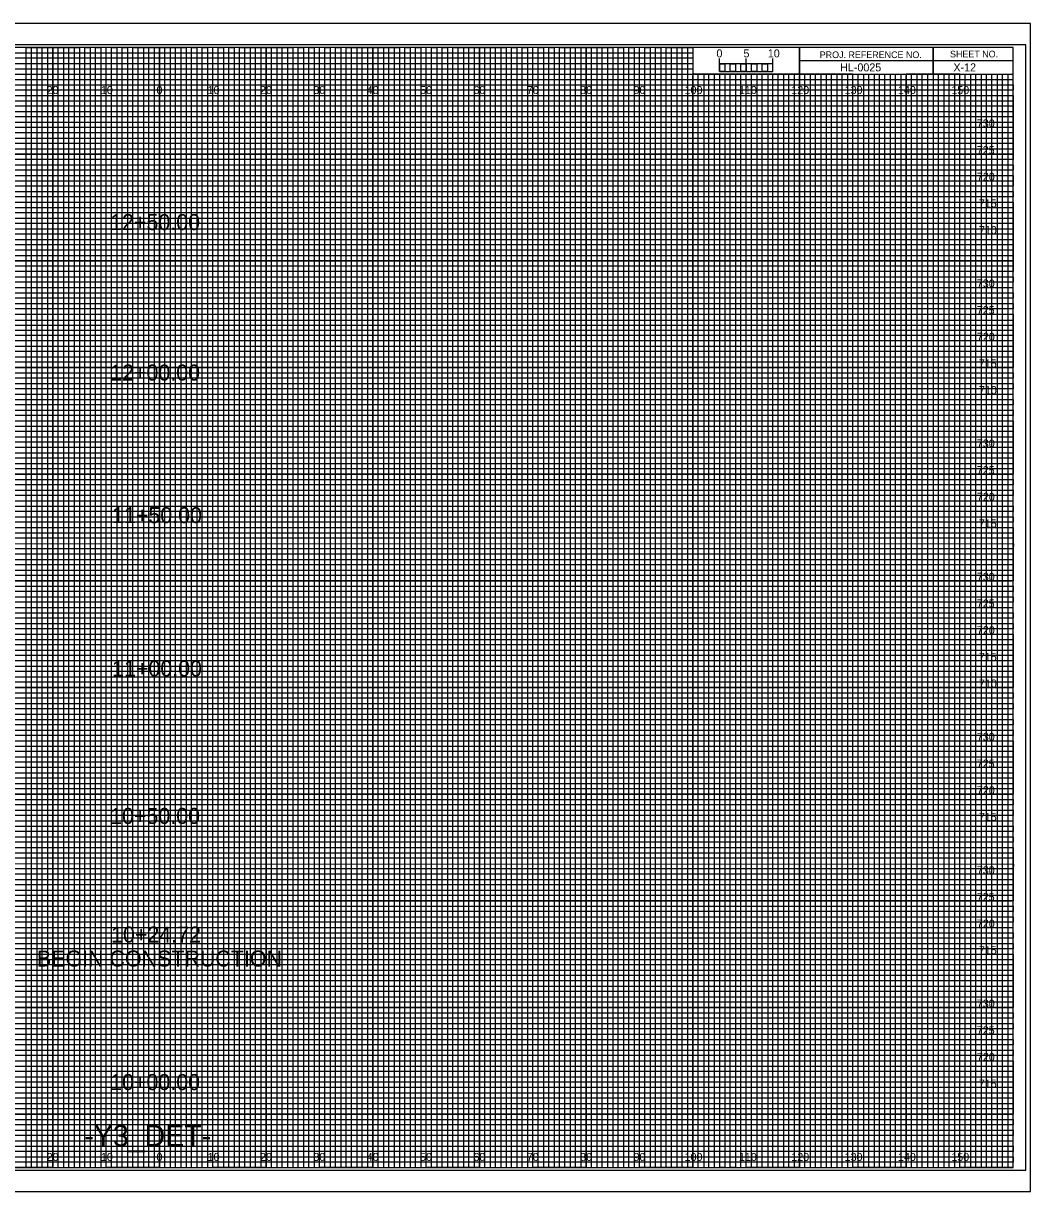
# Model space of a CAD drawing. Extents: x -13 to 323, y -5 to 434.
# Drawn here: x 134.5 to 323.3, y -4.5 to 214.5 of the extents above; entities that cross this region are included whole.
import ezdxf

# ---------------------------------------------------------------- set-up
doc = ezdxf.new("R2010")
doc.units = 0
for name, color, linetype in [('Exist CMT Pavement', 7, 'Continuous'), ('Exist Cross Section Cell', 7, 'Continuous'), ('Exist XS Center Line Elevation Label', 7, 'Continuous'), ('Exist XS Ground Line', 7, 'Continuous'), ('Prop CMT Pvmt Course 1', 7, 'Continuous'), ('Prop CMT Pvmt Course 1 Wedge', 7, 'Continuous'), ('Prop CMT Pvmt Course 2', 7, 'Continuous'), ('Prop CMT Pvmt Course 3', 7, 'Continuous'), ('Prop CMT Pvmt Surface', 7, 'Continuous'), ('Prop CMT Pvmt Surface Shoulder', 7, 'Continuous'), ('Prop CMT Shld Paved Course 1', 7, 'Continuous'), ('Prop CMT Shld Paved Course 2', 7, 'Continuous'), ('Prop CMT Shld Paved Course 3', 7, 'Continuous'), ('Prop CMT Slope Grass', 7, 'Continuous'), ('Prop CMT Subgrade Earthwork', 7, 'Continuous'), ('Prop XS Earthwork Shape', 7, 'Continuous'), ('Scratch_Level_1', 7, 'Continuous')]:
    doc.layers.add(name, color=color, linetype=linetype)

msp = doc.modelspace()

# ---------------------------------------------------------------- linework, layer by layer
at = {"layer": 'Prop CMT Pvmt Course 1'}
msp.add_lwpolyline([(-10.8, -0.5), (322.4, -0.5), (322.4, 210.5), (-10.8, 210.5)], close=True, dxfattribs=at)
at = {"layer": 'Prop CMT Pvmt Course 2'}
for p, q in [((140, 0), (140, 210)), ((150, 0), (150, 210)), ((160, 0), (160, 210)), ((170, 0), (170, 210)), ((180, 0), (180, 210)), ((190, 0), (190, 210)), ((200, 0), (200, 210)), ((210, 0), (210, 210)), ((220, 0), (220, 210)), ((230, 0), (230, 210)), ((240, 0), (240, 210)), ((250, 0), (250, 210)), ((260, 0), (260, 204.69)), ((270, 0), (270, 204.69)), ((280, 0), (280, 204.69)), ((290, 0), (290, 204.69)), ((300, 0), (300, 204.69)), ((310, 0), (310, 204.69)), ((0, 200), (320, 200)), ((0, 190), (320, 190)), ((0, 180), (320, 180)), ((0, 170), (320, 170)), ((0, 160), (320, 160)), ((0, 150), (320, 150)), ((0, 140), (320, 140)), ((0, 130), (320, 130)), ((0, 120), (320, 120)), ((0, 110), (320, 110)), ((0, 100), (320, 100)), ((0, 90), (320, 90)), ((0, 80), (320, 80)), ((0, 70), (320, 70)), ((0, 60), (320, 60)), ((0, 50), (320, 50)), ((0, 40), (320, 40)), ((0, 30), (320, 30)), ((0, 20), (320, 20)), ((0, 10), (320, 10))]:
    msp.add_line(p, q, dxfattribs=at)
at = {"layer": 'Prop CMT Pvmt Course 3'}
for p, q in [((323.3, 214.5), (-13.4, 214.5)), ((-13.4, -4.5), (323.3, -4.5))]:
    msp.add_line(p, q, dxfattribs=at)
at = {"layer": 'Prop CMT Pvmt Surface'}
for p, q in [((265, 205.49), (265, 207.9)), ((265, 206.9), (265, 207.9)), ((270, 205.49), (270, 207.9)), ((275, 205.49), (275, 207.9)), ((275, 206.9), (275, 207.9))]:
    msp.add_line(p, q, dxfattribs=at)
for points in [[(275, 206.9), (265, 206.9), (265, 205.49), (275, 205.49)], [(265, 206.9), (266, 206.9), (266, 205.49), (265, 205.49)], [(267, 206.9), (268, 206.9), (268, 205.49), (267, 205.49)], [(269, 206.9), (270, 206.9), (270, 205.49), (269, 205.49)], [(271, 206.9), (272, 206.9), (272, 205.49), (271, 205.49)], [(273, 206.9), (274, 206.9), (274, 205.49), (273, 205.49)]]:
    msp.add_lwpolyline(points, close=True, dxfattribs=at)
at = {"layer": 'Prop CMT Pvmt Surface Shoulder'}
msp.add_lwpolyline([(-13.4, -4.5), (323.3, -4.5), (323.3, 214.5), (-13.4, 214.5)], close=True, dxfattribs=at)
at = {"layer": 'Prop CMT Shld Paved Course 1'}
for points in [[(125, 0), (135, 0), (135, 210), (145, 210), (145, 0), (155, 0), (155, 210), (165, 210), (165, 0), (175, 0), (175, 210), (185, 210), (185, 0), (195, 0), (195, 210), (205, 210), (205, 0), (215, 0), (215, 210), (225, 210), (225, 0), (235, 0), (235, 210), (245, 210), (245, 0), (255, 0), (255, 210), (259.93, 210), (260, 210), (260, 205), (264.99, 205), (264.99, 0), (275, 0), (275, 205), (285, 205), (285, 0), (295, 0), (295, 205), (305, 205), (305, 0), (315, 0), (315, 205)], [(0, 205), (275, 205)], [(0, 185), (320, 185), (320, 195), (0, 195)], [(0, 165), (320, 165), (320, 175), (0, 175)], [(0, 145), (320, 145), (320, 155), (0, 155)], [(0, 125), (320, 125), (320, 135), (0, 135)], [(0, 105), (320, 105), (320, 115), (0, 115)], [(0, 85), (320, 85), (320, 95), (0, 95)], [(0, 65), (320, 65), (320, 75), (0, 75)], [(0, 45), (320, 45), (320, 55), (0, 55)], [(0, 25), (320, 25), (320, 35), (0, 35)], [(0, 5), (320, 5), (320, 15), (0, 15)]]:
    msp.add_lwpolyline(points, dxfattribs=at)
at = {"layer": 'Prop CMT Shld Paved Course 2'}
for p, q in [((0, 209), (260, 209)), ((260, 209), (260, 207.98)), ((260, 207.98), (0, 207.98)), ((0, 207), (260, 207)), ((260, 205.89), (0, 205.89)), ((260, 207), (260, 205.89)), ((0, 204), (320, 204))]:
    msp.add_line(p, q, dxfattribs=at)
for points in [[(0, 203), (270, 203), (320, 203), (320, 202), (0, 202)], [(0, 201), (320, 201), (320, 199), (0, 199)], [(0, 198), (320, 198), (320, 197), (0, 196.98)], [(0, 196), (320, 196), (320, 194), (0, 194)], [(0, 193), (320, 193), (320, 192), (0, 192)], [(0, 191), (320, 191), (320, 189), (0, 189)], [(0, 188), (320, 188), (320, 187), (0, 187)], [(0, 186), (320, 186), (320, 184), (0, 184)], [(0, 183), (320, 183), (320, 182), (0, 182)], [(0, 181), (320, 181), (320, 179), (0, 179)], [(0, 178), (320, 178), (320, 177), (0, 177)], [(0, 176), (320, 176), (320, 173.95), (320, 173), (320, 172), (0, 172)], [(0, 174), (320, 174), (320, 173), (0, 173)], [(0, 171), (320, 171), (320, 169), (0, 169.03)], [(0, 169.03), (320, 169), (320, 168), (0, 168)], [(0, 167), (320, 167), (320, 166), (0, 166)], [(0, 164), (320, 164), (320, 163), (0, 163)], [(0, 162), (320, 162), (320, 161), (0, 161)], [(-0.07, 158.89), (320, 158.89), (320, 157.88), (-0.07, 157.88)], [(0, 157), (320, 157), (320, 156), (0, 156)], [(0, 154), (320, 154), (320, 153), (0, 153)], [(0, 152), (320, 152), (320, 151), (0, 151)], [(0, 149), (320, 149), (320, 148), (0, 148)], [(0, 147), (320, 147), (320, 146), (0, 146)], [(0, 144), (320, 144), (320, 143), (0, 143)], [(0, 142), (320, 142), (320, 141), (0, 141)], [(0, 139), (320, 139), (319.99, 137.98), (0, 138)], [(0, 137), (320, 137), (320, 136), (0, 136)], [(0, 134), (320, 134), (320, 133), (0, 133)], [(0, 132), (320, 132), (320, 131), (0, 131)], [(0, 129), (320, 129), (320, 128), (0, 128)], [(0, 127), (320, 127), (320, 126), (0, 126)], [(0, 124), (320, 124), (320, 123), (0, 123)], [(0, 122), (320, 122), (320, 121), (0, 121)], [(0, 119), (320, 119), (320, 118), (0, 118)], [(0, 116.99), (320.07, 116.91), (320, 116), (0, 116)], [(0, 114), (320, 114), (320, 113), (0, 113)], [(0, 112), (320, 112), (320, 111), (0, 111)], [(0, 109), (320, 109), (320, 108), (0, 108)], [(0, 107), (320, 107), (320, 106), (0, 106)], [(0, 104), (320, 104), (320, 103), (0, 103)], [(0, 102), (320, 102), (320, 101), (0, 101)], [(0, 99), (320, 99), (320, 98), (0, 98)], [(0, 97), (320, 97), (320, 96), (0, 96)], [(0, 94), (320, 94), (320, 93), (0, 93)], [(0, 92), (320, 92), (320, 91), (0, 91)], [(0, 89), (320, 89), (320, 88), (0, 88)], [(0, 87), (320, 87), (320, 86), (0, 86)], [(0, 84), (320, 84), (320, 83), (0, 83)], [(0, 82), (320, 82), (320, 81), (0, 81)], [(0, 79), (320, 79), (319.99, 77.98), (0, 78)], [(0, 77), (320, 77), (320, 76), (0, 76)], [(0, 74), (320, 74), (320, 73), (0, 73)], [(0, 72), (320, 72), (320, 71), (0, 71)], [(0, 69), (320, 69), (320, 68), (0, 68)], [(0, 67), (320, 67), (320, 66), (0, 66)], [(0, 64), (320, 64), (320, 63), (0, 63)], [(0, 62), (320, 62), (320, 61), (0, 61)], [(0, 59), (320, 59), (320, 58), (0, 58)], [(0, 56.99), (320.07, 56.91), (320, 56), (0, 56)], [(0, 54), (320, 54), (320, 53), (0, 53)], [(0, 52), (320, 52), (320, 51), (0, 51)], [(0, 49), (320, 49), (320, 48), (0, 48)], [(0, 47), (320, 47), (320, 46), (0, 46)], [(0, 44), (320, 44), (320, 43), (0, 43)], [(0, 42), (320, 42), (320, 41), (0, 41)], [(0, 39), (320, 39), (320, 38), (0, 38)], [(0, 37), (320, 37), (320, 36), (0, 36)], [(0, 34), (320, 34), (320, 33), (0, 33)], [(0, 32), (320, 32), (320, 31), (0, 31)], [(0, 29), (320, 29), (320, 28), (0, 28)], [(0, 27), (320, 27), (320, 26), (0, 26)], [(0, 24), (320, 24), (320, 23), (0, 23)], [(0, 22), (320, 22), (320, 21), (0, 21)], [(0, 19), (320, 19), (320, 18), (0, 18)], [(0, 17), (320, 17), (320, 16), (0, 16)], [(0, 14), (320, 14), (320, 13), (0, 13)], [(0, 12), (320, 12), (320, 11), (0, 11)], [(0, 9), (320, 9), (320, 8), (0, 8)], [(0, 7), (320, 7), (320, 6), (0, 6)], [(0, 4), (320, 4), (320, 3), (0, 3)], [(0, 2), (320, 2), (320, 1), (0, 1)]]:
    msp.add_lwpolyline(points, dxfattribs=at)
at = {"layer": 'Prop CMT Shld Paved Course 3'}
for p, q in [((305, 210), (305, 205)), ((305, 205), (305, 210)), ((280, 207.5), (280, 205)), ((320, 207.49), (280, 207.49)), ((280, 205), (320, 205))]:
    msp.add_line(p, q, dxfattribs=at)
for points in [[(320, 210), (0, 210), (0, 0), (320, 0)], [(280, 210), (260, 210), (260, 205.03), (280, 205.03)], [(320, 210), (280, 210), (280, 205), (320, 205)]]:
    msp.add_lwpolyline(points, close=True, dxfattribs=at)
at = {"layer": 'Prop CMT Subgrade Earthwork'}
for p, q in [((267, 205), (266.01, 205)), ((266.01, 205), (266.01, 0)), ((267, 0), (267, 205)), ((269, 205), (268, 205)), ((268, 205), (268, 0)), ((269, 0), (269, 205)), ((266.01, 0), (265, 0)), ((268, 0), (267, 0))]:
    msp.add_line(p, q, dxfattribs=at)
for points in [[(135, 0), (136, 0), (136, 210), (137, 210), (137, 0)], [(137, 0), (138, 0), (138, 210), (139, 210), (139, 0)], [(140, 0), (141, 0), (141, 210), (142, 210), (142, 0)], [(142, 0), (143, 0), (143, 210), (144, 210), (144, 0)], [(145, 0), (146, 0), (146, 210), (147, 210), (147, 0)], [(147, 0), (148, 0), (148, 210), (149, 210), (149, 0)], [(150, 0), (151, 0), (151, 210), (152, 210), (152, 0)], [(152, 0), (153, 0), (153, 210), (154, 210), (154, 0)], [(155, 0), (156, 0), (156, 210), (157, 210), (157, 0)], [(157, 0), (158, 0), (158, 210), (159, 210), (159, 0)], [(160, 0), (161, 0), (161, 210), (162, 210), (162, 0)], [(162, 0), (163, 0), (163, 210), (164, 210), (164, 0)], [(165, 0), (166, 0), (166, 210), (167, 210), (167, 0)], [(167, 0), (168, 0), (168, 210), (169, 210), (169, 0)], [(170, 0), (171, 0), (171, 210), (172, 210), (172, 0)], [(172, 0), (173, 0), (173, 210), (174, 210), (174, 0)], [(175, 0), (176, 0), (176, 210), (177, 210), (177, 0)], [(177, 0), (178, 0), (178, 210), (179, 210), (179, 0)], [(180, 0), (181, 0), (181, 210), (182, 210), (182, 0)], [(182, 0), (183, 0), (183, 210), (184, 210), (184, 0)], [(185, 0), (186, 0), (186, 210), (187, 210), (187, 0)], [(187, 0), (188, 0), (188, 210), (189, 210), (189, 0)], [(190, 0), (191, 0), (191, 210), (192, 210), (192, 0)], [(192, 0), (193, 0), (193, 210), (194, 210), (194, 0)], [(195, 0), (196, 0), (196, 210), (197, 210), (197, 0)], [(197, 0), (198, 0), (198, 210), (199, 210), (199, 0)], [(200, 0), (201, 0), (201, 210), (202, 210), (202, 0)], [(202, 0), (203, 0), (203, 210), (204, 210), (204, 0)], [(205, 0), (206, 0), (206, 210), (207, 210), (207, 0)], [(207, 0), (208, 0), (208, 210), (209, 210), (209, 0)], [(210, 0), (211, 0), (211, 210), (212, 210), (212, 0)], [(212, 0), (213, 0), (213, 210), (214, 210), (214, 0)], [(215, 0), (216, 0), (216, 210), (217, 210), (217, 0)], [(217, 0), (218, 0), (218, 210), (219, 210), (219, 0)], [(220, 0), (221, 0), (221, 210), (222, 210), (222, 0)], [(222, 0), (223, 0), (223, 210), (224, 210), (224, 0)], [(225, 0), (226, 0), (226, 210), (227, 210), (227, 0)], [(227, 0), (228, 0), (228, 210), (229, 210), (229, 0)], [(230, 0), (231, 0), (231, 210), (232, 210), (232, 0)], [(232, 0), (233, 0), (233, 210), (234, 210), (234, 0)], [(235, 0), (236, 0), (236, 210), (237, 210), (237, 0)], [(237, 0), (238, 0), (238, 210), (239, 210), (239, 0)], [(240, 0), (241, 0), (241, 210), (242, 210), (242, 0)], [(242, 0), (243, 0), (243, 210), (244, 210), (244, 0)], [(245, 0), (246, 0), (246, 210), (247, 210), (247, 0)], [(247, 0), (248, 0), (248, 210), (249, 210), (249, 0)], [(250, 0), (251, 0), (251, 210), (252, 210), (252, 0)], [(252, 0), (253, 0), (253, 210), (254, 210), (254, 0)], [(255, 0), (256, 0), (256, 210), (257, 210), (257, 0)], [(257, 0), (258, 0), (258, 210), (259, 210), (259, 0)], [(260, 0), (261, 0), (261, 205), (262.02, 205), (262.02, 0)], [(262, 0), (263, 0), (263, 205), (263.99, 205), (263.99, 0)], [(270, 0), (270.98, 0), (270.98, 205), (272, 205), (272, 0)], [(272, 0), (273, 0), (273, 205), (274.05, 205), (274.05, 0)], [(275, 0), (276, 0), (276, 205), (277, 205), (277, 0)], [(277, 0), (278, 0), (278, 205), (279, 205), (279, 0)], [(280, 0), (281, 0), (281, 205), (282, 205), (282, 0)], [(282, 0), (283, 0), (283, 205), (284, 205), (284, 0)], [(285, 0), (286, 0), (286, 205), (287, 205), (287, 0)], [(287, 0), (288, 0), (288, 205), (289, 205), (289, 0)], [(290, 0), (291, 0), (291, 205), (292, 205), (292, 0)], [(292, 0), (293, 0), (293, 205), (294, 205), (294, 0)], [(295, 0), (296, 0), (296, 205), (297, 205), (297, 0)], [(297, 0), (298, 0), (298, 205), (299, 205), (299, 0)], [(300, 0), (301, 0), (301, 205), (302, 205), (302, 0)], [(302, 0), (303, 0), (303, 205), (304, 205), (304, 0)], [(305, 0), (306, 0), (306, 205), (307, 205), (307, 0)], [(307, 0), (308, 0), (308, 205), (309, 205), (309, 0)], [(310, 0), (311, 0), (311, 205), (312, 205), (312, 0)], [(312, 0), (313, 0), (313, 205), (314, 205), (314, 0)], [(315, 0), (316, 0), (316, 205), (317, 205), (317, 0)], [(317, 0), (318, 0), (318, 205), (319, 205), (319, 0)]]:
    msp.add_lwpolyline(points, dxfattribs=at)
at = {"layer": 'Scratch_Level_1'}
for p, q in [((150, 210), (140, 210)), ((140, 210), (140, 0)), ((150, 0), (150, 210)), ((170, 210), (160, 210)), ((160, 210), (160, 0)), ((170, 0), (170, 210)), ((190, 210), (180, 210)), ((180, 210), (180, 0)), ((190, 0), (190, 210)), ((210, 210), (200, 210)), ((200, 210), (200, 0)), ((210, 0), (210, 210)), ((230, 210), (220, 210)), ((220, 210), (220, 0)), ((230, 0), (230, 210)), ((250, 210), (240, 210)), ((240, 210), (240, 0)), ((250, 0), (250, 210)), ((260, 210), (260, 0)), ((270, 0), (270, 205)), ((290, 205), (280, 205)), ((280, 205), (280, 0)), ((290, 0), (290, 205)), ((310, 205), (300, 205)), ((300, 205), (300, 0)), ((310, 0), (310, 205)), ((140, 0), (130, 0)), ((160, 0), (150, 0)), ((180, 0), (170, 0)), ((200, 0), (190, 0)), ((220, 0), (210, 0)), ((240, 0), (230, 0)), ((260, 0), (250, 0)), ((280, 0), (270, 0)), ((300, 0), (290, 0)), ((320, 0), (310, 0)), ((320, 0), (320, 0))]:
    msp.add_line(p, q, dxfattribs=at)
for points in [[(0, 200), (320, 200), (320, 190), (0, 190)], [(0, 180), (320, 180), (320, 170), (0, 170)], [(0, 160), (320, 160), (320, 150), (0, 150)], [(0, 140), (320, 140), (320, 130), (0, 130)], [(0, 120), (320, 120), (320, 110), (0, 110)], [(0, 100), (320, 100), (320, 90), (0, 90)], [(0, 80), (320, 80), (320, 70), (0, 70)], [(0, 60), (320, 60), (320, 50), (0, 50)], [(0, 40), (320, 40), (320, 30), (0, 30)], [(0, 20), (320, 20), (320, 10), (0, 10)]]:
    msp.add_lwpolyline(points, dxfattribs=at)

# ---------------------------------------------------------------- texts
at = {"layer": 'Exist CMT Pavement'}
for s, p in [('5', (269.47, 208.12)), ('10', (274.04, 208.12))]:
    msp.add_text(s, height=1.5, dxfattribs=at).set_placement(p)
at = {"layer": 'Exist Cross Section Cell'}
for s, p in [('20', (138.86, 201.25)), ('10', (149.04, 201.25)), ('0', (159.45, 201.25)), ('0', (159.45, 201.25)), ('10', (169.04, 201.25)), ('20', (178.86, 201.25)), ('30', (188.86, 201.25)), ('40', (198.86, 201.25)), ('50', (208.86, 201.25)), ('60', (218.86, 201.25)), ('70', (228.86, 201.25)), ('80', (238.86, 201.25)), ('90', (248.86, 201.25)), ('100', (258.44, 201.25)), ('110', (268.62, 201.25)), ('120', (278.44, 201.25)), ('130', (288.44, 201.25)), ('140', (298.44, 201.25)), ('150', (308.44, 201.25)), ('20', (138.86, 1.25)), ('10', (149.04, 1.25)), ('0', (159.45, 1.25)), ('0', (159.45, 1.25)), ('10', (169.04, 1.25)), ('20', (178.86, 1.25)), ('30', (188.86, 1.25)), ('40', (198.86, 1.25)), ('50', (208.86, 1.25)), ('60', (218.86, 1.25)), ('70', (228.86, 1.25)), ('80', (238.86, 1.25)), ('90', (248.86, 1.25)), ('100', (258.44, 1.25)), ('110', (268.62, 1.25)), ('120', (278.44, 1.25)), ('130', (288.44, 1.25)), ('140', (298.44, 1.25)), ('150', (308.44, 1.25))]:
    msp.add_text(s, height=1.5, dxfattribs=at).set_placement(p)
at = {"layer": 'Exist XS Center Line Elevation Label'}
msp.add_text('X-12', height=1.5, dxfattribs=at).set_placement((308.83, 205.5))
at = {"layer": 'Exist XS Ground Line'}
for s, p in [('12+50.00', (150.77, 175.75)), ('12+00.00', (150.77, 147.54)), ('11+50.00', (151.13, 120.81)), ('11+00.00', (151.13, 92.08)), ('10+50.00', (150.77, 64.43)), ('10+24.72', (150.94, 42.2)), ('BEGIN CONSTRUCTION', (137.05, 37.7)), ('10+00.00', (150.77, 14.54))]:
    msp.add_text(s, height=3, dxfattribs=at).set_placement(p)
at = {"layer": 'Prop CMT Pvmt Course 1 Wedge'}
msp.add_text('-Y3_DET-', height=4, dxfattribs=at).set_placement((145.93, 4))
at = {"layer": 'Prop CMT Pvmt Surface'}
msp.add_text('0', height=1.5, dxfattribs=at).set_placement((264.41, 208.12))
at = {"layer": 'Prop CMT Shld Paved Course 3'}
for s, p in [('PROJ. REFERENCE NO.', (283.77, 207.99)), ('SHEET NO.', (308.19, 208.12))]:
    msp.add_text(s, height=1.25, dxfattribs=at).set_placement(p)
at = {"layer": 'Prop CMT Slope Grass'}
for s, p in [('730', (313.22, 195)), ('725', (313.21, 190)), ('720', (313.23, 185)), ('715', (313.59, 180)), ('710', (313.61, 175)), ('730', (313.22, 165)), ('725', (313.21, 160)), ('720', (313.23, 155)), ('715', (313.59, 150)), ('710', (313.61, 145)), ('730', (313.22, 135)), ('725', (313.21, 130)), ('720', (313.23, 125)), ('715', (313.59, 120)), ('730', (313.22, 110)), ('725', (313.21, 105)), ('720', (313.23, 100)), ('715', (313.59, 95)), ('710', (313.61, 90)), ('730', (313.22, 80)), ('725', (313.21, 75)), ('720', (313.23, 70)), ('715', (313.59, 65)), ('730', (313.22, 55)), ('725', (313.21, 50)), ('720', (313.23, 45)), ('715', (313.59, 40)), ('730', (313.22, 30)), ('725', (313.21, 25)), ('720', (313.23, 20)), ('715', (313.59, 15))]:
    msp.add_text(s, height=1.5, dxfattribs=at).set_placement(p)
at = {"layer": 'Prop XS Earthwork Shape'}
msp.add_text('HL-0025', height=1.5, dxfattribs=at).set_placement((287.6, 205.5))

doc.saveas('drawing.dxf')
